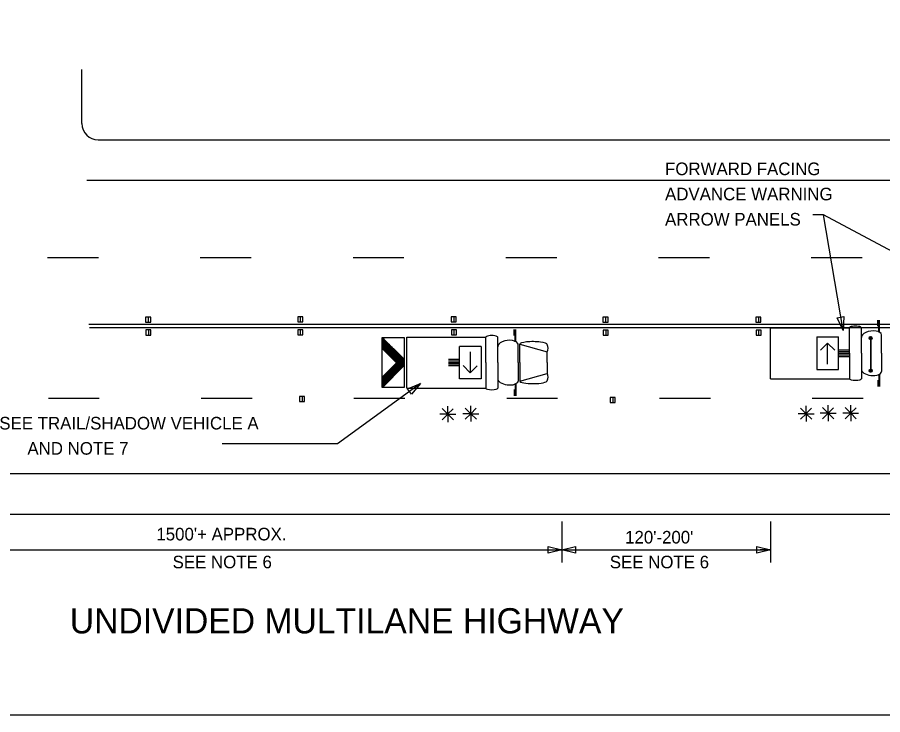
# Model space of a CAD drawing. Extents: x 1806907 to 1812607, y 675071 to 676228.
# Drawn here: x 1811195.1 to 1811607.3, y 675071.2 to 675403.2 of the extents above; entities that cross this region are included whole.
import ezdxf

# ---------------------------------------------------------------- set-up
doc = ezdxf.new("R2010")
doc.units = 0
for name, color, linetype in [('DSN_DRFT_Named-Boundary', 7, 'Continuous'), ('Level 1', 7, 'Continuous'), ('Working Level 1', 7, 'Continuous')]:
    doc.layers.add(name, color=color, linetype=linetype)

msp = doc.modelspace()

# ---------------------------------------------------------------- linework, layer by layer
at = {"layer": 'DSN_DRFT_Named-Boundary'}
msp.add_lwpolyline([(1810956.68, 675071.2), (1812606.68, 675071.2), (1812606.68, 676121.2), (1810956.68, 676121.2)], close=True, dxfattribs=at)
at = {"layer": 'Level 1'}
msp.add_lwpolyline([(1811387.1, 675228.88), (1811347.53, 675200.17), (1811292.64, 675200.17)], dxfattribs=at)
at = {"layer": 'Working Level 1'}
for p, q in [((1811225.9, 675352.65), (1811225.9, 675378.34)), ((1811233.66, 675344.89), (1811756.74, 675344.89)), ((1811228.24, 675325.65), (1811756.74, 675325.65)), ((1811704.26, 675242.22), (1811579.1, 675309.23)), ((1811256.22, 675260.51), (1811256.21, 675258.08)), ((1811258.64, 675260.51), (1811256.22, 675260.51)), ((1811257.44, 675260.51), (1811257.43, 675258.08)), ((1811258.64, 675258.08), (1811258.64, 675260.51)), ((1811328.66, 675260.69), (1811328.65, 675258.26)), ((1811331.08, 675260.69), (1811328.66, 675260.69)), ((1811329.88, 675260.69), (1811329.87, 675258.26)), ((1811331.08, 675258.26), (1811331.08, 675260.69)), ((1811404.18, 675260.61), (1811401.75, 675260.61)), ((1811401.75, 675260.61), (1811401.75, 675258.18)), ((1811402.97, 675260.61), (1811402.96, 675258.18)), ((1811404.18, 675258.18), (1811404.18, 675260.61)), ((1811476.45, 675260.47), (1811474.02, 675260.47)), ((1811474.02, 675260.47), (1811474.02, 675258.04)), ((1811475.24, 675260.47), (1811475.23, 675258.04)), ((1811476.45, 675258.04), (1811476.45, 675260.47)), ((1811546.86, 675260.47), (1811546.85, 675258.04)), ((1811549.28, 675260.47), (1811546.86, 675260.47)), ((1811548.08, 675260.47), (1811548.07, 675258.04)), ((1811549.28, 675258.04), (1811549.28, 675260.47)), ((1811229.23, 675257.17), (1811756.74, 675257.17)), ((1811229.57, 675255.48), (1811756.74, 675255.48)), ((1811256.21, 675258.08), (1811258.64, 675258.08)), ((1811328.65, 675258.26), (1811331.08, 675258.26)), ((1811401.75, 675258.18), (1811404.18, 675258.18)), ((1811474.02, 675258.04), (1811476.45, 675258.04)), ((1811546.85, 675258.04), (1811549.28, 675258.04)), ((1811553.82, 675255.43), (1811591.37, 675255.43)), ((1811553.82, 675231.17), (1811553.82, 675255.43)), ((1811591.37, 675243.3), (1811591.37, 675255.43)), ((1811597.12, 675243.3), (1811597.12, 675255.43)), ((1811604.87, 675256.16), (1811604.87, 675259.12)), ((1811605.34, 675253.3), (1811605.34, 675259.12)), ((1811605.74, 675253.3), (1811605.74, 675259.12)), ((1811256.33, 675254.4), (1811256.32, 675251.97)), ((1811256.32, 675251.97), (1811258.75, 675251.97)), ((1811258.75, 675254.4), (1811256.33, 675254.4)), ((1811257.55, 675254.4), (1811257.54, 675251.97)), ((1811258.75, 675251.97), (1811258.75, 675254.4)), ((1811328.69, 675254.51), (1811328.68, 675252.08)), ((1811328.68, 675252.08), (1811331.11, 675252.08)), ((1811331.11, 675254.51), (1811328.69, 675254.51)), ((1811329.9, 675254.51), (1811329.9, 675252.08)), ((1811331.11, 675252.08), (1811331.11, 675254.51)), ((1811401.86, 675254.44), (1811401.85, 675252.01)), ((1811401.85, 675252.01), (1811404.28, 675252.01)), ((1811404.28, 675254.44), (1811401.86, 675254.44)), ((1811403.08, 675254.44), (1811403.07, 675252.01)), ((1811404.28, 675252.01), (1811404.28, 675254.44)), ((1811431.7, 675251.67), (1811431.7, 675254.64)), ((1811432.17, 675248.81), (1811432.17, 675254.64)), ((1811432.56, 675248.81), (1811432.56, 675254.64)), ((1811474.13, 675254.3), (1811474.12, 675251.87)), ((1811474.12, 675251.87), (1811476.55, 675251.87)), ((1811476.55, 675254.3), (1811474.13, 675254.3)), ((1811475.35, 675254.3), (1811475.34, 675251.87)), ((1811476.55, 675251.87), (1811476.55, 675254.3)), ((1811546.97, 675254.3), (1811546.96, 675251.87)), ((1811546.96, 675251.87), (1811549.39, 675251.87)), ((1811549.39, 675254.3), (1811546.97, 675254.3)), ((1811548.18, 675254.3), (1811548.18, 675251.87)), ((1811549.39, 675251.87), (1811549.39, 675254.3)), ((1811606.76, 675243.3), (1811606.76, 675252.04)), ((1811368.94, 675250.76), (1811379.3, 675240.41)), ((1811380.64, 675250.94), (1811418.19, 675250.94)), ((1811380.64, 675226.69), (1811380.64, 675250.94)), ((1811418.19, 675238.82), (1811418.19, 675250.94)), ((1811423.94, 675238.82), (1811423.94, 675250.94)), ((1811433.58, 675238.82), (1811433.58, 675247.55)), ((1811434.38, 675247.55), (1811447.51, 675243.96)), ((1811434.38, 675238.82), (1811434.38, 675247.55)), ((1811575.88, 675251.07), (1811586.14, 675251.07)), ((1811575.88, 675251.07), (1811575.88, 675235.54)), ((1811581.01, 675248.1), (1811577.71, 675244.81)), ((1811581.01, 675238.17), (1811581.01, 675248.1)), ((1811581.01, 675248.1), (1811584.38, 675244.73)), ((1811586.14, 675235.54), (1811586.14, 675251.07)), ((1811600.78, 675250.68), (1811600.78, 675250.68)), ((1811601.4, 675250.33), (1811601.4, 675235.27)), ((1811601.44, 675250.33), (1811601.44, 675235.27)), ((1811601.49, 675250.33), (1811601.49, 675235.27)), ((1811601.57, 675250.33), (1811601.57, 675235.27)), ((1811601.66, 675251.18), (1811601.66, 675251.18)), ((1811601.68, 675250.33), (1811601.68, 675235.27)), ((1811368.94, 675245.59), (1811375.77, 675238.78)), ((1811415.99, 675246.58), (1811405.72, 675246.58)), ((1811405.72, 675231.05), (1811405.72, 675246.58)), ((1811410.86, 675243.94), (1811410.86, 675234.01)), ((1811415.99, 675246.58), (1811415.99, 675231.05)), ((1811447.51, 675238.82), (1811447.51, 675243.96)), ((1811586.14, 675244.85), (1811591.37, 675244.85)), ((1811586.14, 675244.08), (1811591.37, 675244.08)), ((1811586.14, 675243.3), (1811591.37, 675243.3)), ((1811591.37, 675243.3), (1811591.37, 675231.18)), ((1811597.12, 675243.3), (1811597.12, 675231.18)), ((1811606.76, 675243.3), (1811606.76, 675234.57)), ((1811405.72, 675240.36), (1811400.5, 675240.36)), ((1811405.72, 675239.59), (1811400.5, 675239.59)), ((1811586.14, 675242.53), (1811591.37, 675242.53)), ((1811586.14, 675241.75), (1811591.37, 675241.75)), ((1811368.94, 675231.96), (1811375.77, 675238.78)), ((1811369, 675226.98), (1811379.25, 675237.23)), ((1811405.72, 675238.81), (1811400.5, 675238.81)), ((1811405.72, 675238.04), (1811400.5, 675238.04)), ((1811405.72, 675237.26), (1811400.5, 675237.26)), ((1811410.86, 675234.01), (1811407.48, 675237.39)), ((1811410.86, 675234.01), (1811414.15, 675237.31)), ((1811418.19, 675238.82), (1811418.19, 675226.69)), ((1811423.94, 675238.82), (1811423.94, 675226.69)), ((1811433.58, 675238.82), (1811433.58, 675230.08)), ((1811434.38, 675238.82), (1811434.38, 675230.08)), ((1811447.51, 675238.82), (1811447.51, 675233.67)), ((1811575.88, 675235.54), (1811586.14, 675235.54)), ((1811600.83, 675235.14), (1811600.83, 675235.14)), ((1811601.7, 675235.65), (1811601.7, 675235.65)), ((1811415.99, 675231.05), (1811405.72, 675231.05)), ((1811434.38, 675230.08), (1811447.51, 675233.67)), ((1811553.82, 675231.18), (1811591.37, 675231.18)), ((1811605.34, 675233.31), (1811605.34, 675227.48)), ((1811605.74, 675233.31), (1811605.74, 675227.48)), ((1811380.64, 675226.69), (1811418.19, 675226.69)), ((1811432.17, 675228.82), (1811432.17, 675223)), ((1811432.56, 675228.82), (1811432.56, 675223)), ((1811604.87, 675230.45), (1811604.87, 675227.48)), ((1811329.51, 675222.77), (1811329.5, 675220.34)), ((1811331.93, 675222.77), (1811329.51, 675222.77)), ((1811330.72, 675222.77), (1811330.72, 675220.34)), ((1811331.93, 675220.34), (1811331.93, 675222.77)), ((1811431.7, 675225.96), (1811431.7, 675223)), ((1811329.5, 675220.34), (1811331.93, 675220.34)), ((1811411.11, 675214.51), (1811411.11, 675218.28)), ((1811477.45, 675222.2), (1811477.44, 675219.77)), ((1811477.44, 675219.77), (1811479.87, 675219.77)), ((1811479.87, 675222.2), (1811477.45, 675222.2)), ((1811478.66, 675222.2), (1811478.66, 675219.77)), ((1811479.87, 675219.77), (1811479.87, 675222.2)), ((1811570.78, 675214.51), (1811570.78, 675218.28)), ((1811581.28, 675214.75), (1811581.28, 675218.52)), ((1811592.02, 675214.75), (1811592.02, 675218.52)), ((1811400.13, 675214.27), (1811396.36, 675214.27)), ((1811400.13, 675214.27), (1811397.47, 675216.93)), ((1811400.13, 675214.27), (1811397.47, 675211.61)), ((1811400.06, 675214.22), (1811402.73, 675216.88)), ((1811400.13, 675214.27), (1811400.13, 675218.04)), ((1811400.13, 675214.27), (1811402.79, 675211.61)), ((1811400.13, 675214.27), (1811400.13, 675210.51)), ((1811400.13, 675214.27), (1811403.89, 675214.27)), ((1811411.11, 675214.51), (1811407.34, 675214.51)), ((1811411.11, 675214.51), (1811408.45, 675217.17)), ((1811411.11, 675214.51), (1811408.45, 675211.85)), ((1811411.04, 675214.46), (1811413.71, 675217.12)), ((1811411.11, 675214.51), (1811413.77, 675211.85)), ((1811411.11, 675214.51), (1811411.11, 675210.75)), ((1811411.11, 675214.51), (1811414.87, 675214.51)), ((1811570.78, 675214.51), (1811567.02, 675214.51)), ((1811570.78, 675214.51), (1811568.12, 675217.17)), ((1811570.78, 675214.51), (1811568.12, 675211.85)), ((1811570.72, 675214.46), (1811573.38, 675217.12)), ((1811570.78, 675214.51), (1811573.44, 675211.85)), ((1811570.78, 675214.51), (1811570.78, 675210.75)), ((1811570.78, 675214.51), (1811574.54, 675214.51)), ((1811581.28, 675214.75), (1811577.52, 675214.75)), ((1811581.28, 675214.75), (1811578.62, 675217.41)), ((1811581.28, 675214.75), (1811578.62, 675212.09)), ((1811581.22, 675214.7), (1811583.88, 675217.36)), ((1811581.28, 675214.75), (1811583.94, 675212.09)), ((1811581.28, 675214.75), (1811581.28, 675210.99)), ((1811581.28, 675214.75), (1811585.04, 675214.75)), ((1811592.02, 675214.75), (1811588.26, 675214.75)), ((1811592.02, 675214.75), (1811589.36, 675217.41)), ((1811592.02, 675214.75), (1811589.36, 675212.09)), ((1811591.96, 675214.7), (1811594.62, 675217.36)), ((1811592.02, 675214.75), (1811594.68, 675212.09)), ((1811592.02, 675214.75), (1811592.02, 675210.99)), ((1811592.02, 675214.75), (1811595.78, 675214.75)), ((1810956.68, 675185.99), (1811756.74, 675185.99)), ((1810956.68, 675166.6), (1811756.74, 675166.6)), ((1811454.42, 675163.13), (1811454.42, 675143.66)), ((1811553.86, 675163.13), (1811553.86, 675143.66)), ((1811137.45, 675149.72), (1811454.42, 675149.72)), ((1811454.42, 675149.72), (1811451.7, 675149.72)), ((1811454.42, 675149.72), (1811459.93, 675149.72)), ((1811454.42, 675149.72), (1811553.86, 675149.72))]:
    msp.add_line(p, q, dxfattribs=at)
for points in [[(1811588.38, 675254.12), (1811579.1, 675309.23), (1811573.91, 675309.23)], [(1811209.48, 675288.91), (1811233.74, 675288.91)], [(1811282.24, 675288.91), (1811306.49, 675288.91)], [(1811354.99, 675288.91), (1811379.25, 675288.91)], [(1811427.75, 675288.91), (1811452, 675288.91)], [(1811500.5, 675288.91), (1811524.76, 675288.91)], [(1811573.26, 675288.91), (1811597.51, 675288.91)], [(1811601.31, 675251.22), (1811602, 675250.02)], [(1811601.46, 675251.25), (1811602.1, 675250.14)], [(1811601.64, 675251.23), (1811602.17, 675250.31)], [(1811368.94, 675250.21), (1811375.23, 675239.31)], [(1811368.94, 675249.27), (1811373.99, 675240.52)], [(1811368.94, 675248.33), (1811372.74, 675241.75)], [(1811368.94, 675247.4), (1811371.49, 675242.97)], [(1811369.47, 675250.24), (1811377.8, 675235.8)], [(1811370.74, 675248.96), (1811378.14, 675236.14)], [(1811372.02, 675247.68), (1811378.49, 675236.48)], [(1811600.76, 675250.41), (1811601.03, 675249.96)], [(1811600.78, 675250.68), (1811601.27, 675249.83)], [(1811600.84, 675250.86), (1811601.46, 675249.79)], [(1811600.93, 675250.99), (1811601.62, 675249.81)], [(1811601.04, 675251.09), (1811601.76, 675249.85)], [(1811601.16, 675251.18), (1811601.89, 675249.92)], [(1811601.85, 675251.15), (1811602.21, 675250.54)], [(1811368.94, 675246.45), (1811370.25, 675244.19)], [(1811368.94, 675245.52), (1811369, 675245.41)], [(1811373.3, 675246.4), (1811378.83, 675236.82)], [(1811374.58, 675245.13), (1811379.18, 675237.17)], [(1811375.86, 675243.85), (1811379.26, 675237.96)], [(1811377.14, 675242.57), (1811379.27, 675238.88)], [(1811378.41, 675241.3), (1811379.29, 675239.78)], [(1811371.85, 675234.86), (1811373.68, 675231.69)], [(1811372.19, 675235.21), (1811374.02, 675232.04)], [(1811372.53, 675235.55), (1811374.36, 675232.38)], [(1811372.87, 675235.89), (1811374.7, 675232.72)], [(1811373.22, 675236.24), (1811375.05, 675233.06)], [(1811373.56, 675236.58), (1811375.39, 675233.4)], [(1811373.9, 675236.92), (1811375.74, 675233.74)], [(1811374.24, 675237.26), (1811376.08, 675234.09)], [(1811374.59, 675237.61), (1811376.43, 675234.43)], [(1811374.94, 675237.95), (1811376.76, 675234.77)], [(1811375.28, 675238.29), (1811377.11, 675235.12)], [(1811375.62, 675238.64), (1811377.46, 675235.45)], [(1811600.81, 675234.88), (1811601.07, 675234.42)], [(1811600.83, 675235.14), (1811601.31, 675234.3)], [(1811600.89, 675235.33), (1811601.5, 675234.26)], [(1811600.98, 675235.46), (1811601.66, 675234.28)], [(1811601.08, 675235.56), (1811601.8, 675234.32)], [(1811601.2, 675235.64), (1811601.93, 675234.39)], [(1811601.35, 675235.68), (1811602.04, 675234.48)], [(1811601.5, 675235.72), (1811602.14, 675234.61)], [(1811601.68, 675235.7), (1811602.21, 675234.77)], [(1811601.9, 675235.62), (1811602.25, 675235)], [(1811368.94, 675231.46), (1811370.58, 675228.61)], [(1811369.1, 675232.12), (1811370.92, 675228.96)], [(1811369.44, 675232.47), (1811371.27, 675229.3)], [(1811369.78, 675232.8), (1811371.61, 675229.64)], [(1811370.13, 675233.15), (1811371.96, 675229.98)], [(1811370.47, 675233.49), (1811372.3, 675230.33)], [(1811370.81, 675233.83), (1811372.64, 675230.66)], [(1811371.15, 675234.17), (1811372.98, 675231.01)], [(1811371.5, 675234.52), (1811373.33, 675231.35)], [(1811368.94, 675230.52), (1811370.24, 675228.27)], [(1811368.94, 675229.58), (1811369.89, 675227.93)], [(1811368.94, 675228.64), (1811369.55, 675227.58)], [(1811368.94, 675227.7), (1811369.2, 675227.25)], [(1811209.92, 675221.92), (1811234.17, 675221.92)], [(1811282.67, 675221.92), (1811306.93, 675221.92)], [(1811355.43, 675221.92), (1811379.68, 675221.92)], [(1811428.18, 675221.92), (1811452.44, 675221.92)], [(1811500.94, 675221.92), (1811525.19, 675221.92)], [(1811573.69, 675221.92), (1811597.95, 675221.92)], [(1811553.86, 675149.72), (1811548.84, 675149.72), (1811548.84, 675149.37)]]:
    msp.add_lwpolyline(points, dxfattribs=at)
for points in [[(1811588.69, 675260.81), (1811588.38, 675254.12), (1811585.5, 675260.17)], [(1811379.33, 675226.98), (1811368.94, 675226.98), (1811368.94, 675250.76), (1811379.33, 675250.76)], [(1811380.88, 675226.38), (1811387.1, 675228.88), (1811382.79, 675223.75)], [(1811447.92, 675151.35), (1811454.42, 675149.72), (1811447.92, 675148.1)], [(1811460.92, 675148.1), (1811454.42, 675149.72), (1811460.92, 675151.35)], [(1811547.36, 675151.35), (1811553.86, 675149.72), (1811547.36, 675148.1)]]:
    msp.add_lwpolyline(points, close=True, dxfattribs=at)
for centre in [(1811601.48, 675250.52), (1811601.53, 675234.99)]:
    msp.add_circle(centre, 0.728, dxfattribs=at)
for centre, radius, start, end in [((1811233.66, 675352.65), 7.76, 180, 270), ((1811444.29, 675245.68), 3.64, 331.8801, 28.1199), ((1811444.29, 675231.95), 3.64, 331.8801, 28.1199)]:
    msp.add_arc(centre, radius, start, end, dxfattribs=at)
for centre, major_axis, ratio, start_param, end_param in [((1811594.25, 675255.43), (2.88, 0), 0.269913, 0, 3.141593), ((1811421.07, 675250.94), (2.88, 0), 0.269913, 0, 3.141593), ((1811601.94, 675251.44), (4.82, 0.6), 0.503092, 0, 3.141593), ((1811428.76, 675246.95), (4.82, 0.6), 0.503092, 0, 3.141593), ((1811440.94, 675247.48), (6.56, -0.08), 0.2034, 0, 3.141593), ((1811601.94, 675235.16), (4.82, -0.6), 0.503092, 3.141593, 6.283185), ((1811428.76, 675230.68), (4.82, -0.6), 0.503092, 3.141593, 6.283185), ((1811594.25, 675231.18), (2.88, 0), 0.269913, 3.141593, 6.283185), ((1811421.07, 675226.69), (2.88, 0), 0.269913, 3.141593, 6.283185), ((1811440.94, 675230.16), (6.56, 0.08), 0.2034, 3.141593, 6.283185)]:
    msp.add_ellipse(centre, major_axis=major_axis, ratio=ratio, start_param=start_param, end_param=end_param, dxfattribs=at)

# ---------------------------------------------------------------- texts
for s, p in [('FORWARD FACING', (1811503.6, 675328.1)), ('ADVANCE WARNING ', (1811503.6, 675316.1)), ('ARROW PANELS', (1811503.6, 675304.1)), ('SEE TRAIL/SHADOW VEHICLE A', (1811186.55, 675207)), ('      AND NOTE 7', (1811186.55, 675195)), ("1500'+ APPROX.", (1811261.35, 675154.18)), ("120'-200'", (1811484.58, 675152.71)), ('SEE NOTE 6', (1811269.08, 675140.9)), ('SEE NOTE 6', (1811477.28, 675140.9))]:
    msp.add_text(s, height=6, dxfattribs=at).set_placement(p)
msp.add_text('UNDIVIDED MULTILANE HIGHWAY', height=12, rotation=0, dxfattribs=at).set_placement((1811220.1, 675109.91))

doc.saveas('drawing.dxf')
